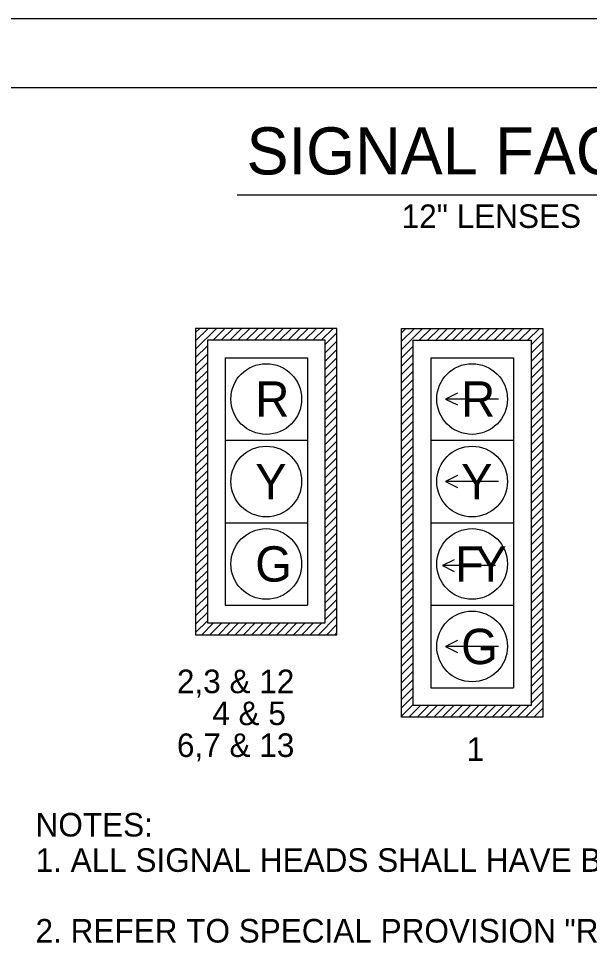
# Model space of a CAD drawing. Extents: x 1709451 to 1710451, y 561684 to 562324.
# Drawn here: x 1709624 to 1709720.9, y 562166.2 to 562324 of the extents above; entities that cross this region are included whole.
import ezdxf

# ---------------------------------------------------------------- set-up
doc = ezdxf.new("R2010")
doc.units = 0
for name, color, linetype in [('E_Existing ROW', 7, 'Continuous'), ('R_Alt Surface', 7, 'Continuous'), ('R_Alt Surface Annot', 7, 'Continuous'), ('R_Detour', 7, 'Continuous')]:
    doc.layers.add(name, color=color, linetype=linetype)

msp = doc.modelspace()

# ---------------------------------------------------------------- linework, layer by layer
at = {"layer": 'E_Existing ROW'}
for p, q in [((1709678.03, 562271.42), (1709654.03, 562271.42)), ((1709654.03, 562271.42), (1709654.03, 562219.42)), ((1709654.03, 562267.88), (1709657.57, 562271.42)), ((1709654.03, 562269.29), (1709656.16, 562271.42)), ((1709654.03, 562270.71), (1709654.74, 562271.42)), ((1709656.99, 562269.42), (1709658.99, 562271.42)), ((1709658.4, 562269.42), (1709660.4, 562271.42)), ((1709659.82, 562269.42), (1709661.82, 562271.42)), ((1709661.23, 562269.42), (1709663.23, 562271.42)), ((1709662.64, 562269.42), (1709664.64, 562271.42)), ((1709664.06, 562269.42), (1709666.06, 562271.42)), ((1709665.47, 562269.42), (1709667.47, 562271.42)), ((1709666.89, 562269.42), (1709668.89, 562271.42)), ((1709668.3, 562269.42), (1709670.3, 562271.42)), ((1709669.72, 562269.42), (1709671.72, 562271.42)), ((1709671.13, 562269.42), (1709673.13, 562271.42)), ((1709672.54, 562269.42), (1709674.54, 562271.42)), ((1709673.96, 562269.42), (1709675.96, 562271.42)), ((1709675.37, 562269.42), (1709677.37, 562271.42)), ((1709676.03, 562268.66), (1709678.03, 562270.66)), ((1709678.03, 562219.42), (1709678.03, 562271.42)), ((1709688.96, 562205.42), (1709688.96, 562271.42)), ((1709688.96, 562271.42), (1709712.96, 562271.42)), ((1709688.96, 562267.82), (1709692.57, 562271.42)), ((1709688.96, 562269.23), (1709691.16, 562271.42)), ((1709688.96, 562270.64), (1709689.74, 562271.42)), ((1709691.99, 562269.42), (1709693.99, 562271.42)), ((1709693.4, 562269.42), (1709695.4, 562271.42)), ((1709694.81, 562269.42), (1709696.81, 562271.42)), ((1709696.23, 562269.42), (1709698.23, 562271.42)), ((1709697.64, 562269.42), (1709699.64, 562271.42)), ((1709699.06, 562269.42), (1709701.06, 562271.42)), ((1709700.47, 562269.42), (1709702.47, 562271.42)), ((1709701.89, 562269.42), (1709703.89, 562271.42)), ((1709703.3, 562269.42), (1709705.3, 562271.42)), ((1709704.71, 562269.42), (1709706.71, 562271.42)), ((1709706.13, 562269.42), (1709708.13, 562271.42)), ((1709707.54, 562269.42), (1709709.54, 562271.42)), ((1709708.96, 562269.42), (1709710.96, 562271.42)), ((1709710.37, 562269.42), (1709712.37, 562271.42)), ((1709712.96, 562271.42), (1709712.96, 562205.42)), ((1709676.03, 562267.25), (1709678.03, 562269.25)), ((1709710.96, 562268.6), (1709712.96, 562270.6)), ((1709710.96, 562267.19), (1709712.96, 562269.19)), ((1709654.03, 562266.46), (1709656.03, 562268.46)), ((1709676.03, 562265.84), (1709678.03, 562267.84)), ((1709688.96, 562266.4), (1709690.96, 562268.4)), ((1709710.96, 562265.77), (1709712.96, 562267.77)), ((1709654.03, 562265.05), (1709656.03, 562267.05)), ((1709659.03, 562266.42), (1709673.03, 562266.42)), ((1709659.03, 562266.42), (1709659.03, 562252.42)), ((1709673.03, 562266.42), (1709673.03, 562252.42)), ((1709676.03, 562264.42), (1709678.03, 562266.42)), ((1709688.96, 562264.99), (1709690.96, 562266.99)), ((1709693.96, 562266.42), (1709707.96, 562266.42)), ((1709693.96, 562266.42), (1709693.96, 562252.42)), ((1709707.96, 562266.42), (1709707.96, 562252.42)), ((1709710.96, 562264.36), (1709712.96, 562266.36)), ((1709654.03, 562263.63), (1709656.03, 562265.63)), ((1709676.03, 562263.01), (1709678.03, 562265.01)), ((1709688.96, 562263.57), (1709690.96, 562265.57)), ((1709710.96, 562262.95), (1709712.96, 562264.95)), ((1709654.03, 562262.22), (1709656.03, 562264.22)), ((1709654.03, 562260.81), (1709656.03, 562262.81)), ((1709676.03, 562261.59), (1709678.03, 562263.59)), ((1709688.96, 562262.16), (1709690.96, 562264.16)), ((1709688.96, 562260.75), (1709690.96, 562262.75)), ((1709710.96, 562261.53), (1709712.96, 562263.53)), ((1709654.03, 562259.39), (1709656.03, 562261.39)), ((1709676.03, 562260.18), (1709678.03, 562262.18)), ((1709688.96, 562259.33), (1709690.96, 562261.33)), ((1709710.96, 562260.12), (1709712.96, 562262.12)), ((1709654.03, 562257.98), (1709656.03, 562259.98)), ((1709676.03, 562258.76), (1709678.03, 562260.76)), ((1709688.96, 562257.92), (1709690.96, 562259.92)), ((1709710.96, 562258.7), (1709712.96, 562260.7)), ((1709654.03, 562256.56), (1709656.03, 562258.56)), ((1709676.03, 562257.35), (1709678.03, 562259.35)), ((1709688.96, 562256.5), (1709690.96, 562258.5)), ((1709705.46, 562259.42), (1709696.46, 562259.42)), ((1709710.96, 562257.29), (1709712.96, 562259.29)), ((1709654.03, 562255.15), (1709656.03, 562257.15)), ((1709676.03, 562255.94), (1709678.03, 562257.94)), ((1709676.03, 562254.52), (1709678.03, 562256.52)), ((1709688.96, 562255.09), (1709690.96, 562257.09)), ((1709710.96, 562255.88), (1709712.96, 562257.88)), ((1709710.96, 562254.46), (1709712.96, 562256.46)), ((1709654.03, 562253.73), (1709656.03, 562255.73)), ((1709676.03, 562253.11), (1709678.03, 562255.11)), ((1709688.96, 562253.67), (1709690.96, 562255.67)), ((1709710.96, 562253.05), (1709712.96, 562255.05)), ((1709654.03, 562252.32), (1709656.03, 562254.32)), ((1709676.03, 562251.69), (1709678.03, 562253.69)), ((1709688.96, 562252.26), (1709690.96, 562254.26)), ((1709710.96, 562251.63), (1709712.96, 562253.63)), ((1709654.03, 562250.91), (1709656.03, 562252.91)), ((1709659.03, 562252.42), (1709673.03, 562252.42)), ((1709659.03, 562252.42), (1709659.03, 562238.42)), ((1709673.03, 562252.42), (1709673.03, 562238.42)), ((1709676.03, 562250.28), (1709678.03, 562252.28)), ((1709688.96, 562250.85), (1709690.96, 562252.85)), ((1709693.96, 562252.42), (1709707.96, 562252.42)), ((1709693.96, 562252.42), (1709693.96, 562238.42)), ((1709707.96, 562252.42), (1709707.96, 562238.42)), ((1709710.96, 562250.22), (1709712.96, 562252.22)), ((1709654.03, 562249.49), (1709656.03, 562251.49)), ((1709676.03, 562248.86), (1709678.03, 562250.86)), ((1709688.96, 562249.43), (1709690.96, 562251.43)), ((1709710.96, 562248.8), (1709712.96, 562250.8)), ((1709654.03, 562248.08), (1709656.03, 562250.08)), ((1709654.03, 562246.66), (1709656.03, 562248.66)), ((1709676.03, 562247.45), (1709678.03, 562249.45)), ((1709688.96, 562248.02), (1709690.96, 562250.02)), ((1709688.96, 562246.6), (1709690.96, 562248.6)), ((1709710.96, 562247.39), (1709712.96, 562249.39)), ((1709654.03, 562245.25), (1709656.03, 562247.25)), ((1709676.03, 562246.04), (1709678.03, 562248.04)), ((1709688.96, 562245.19), (1709690.96, 562247.19)), ((1709710.96, 562245.98), (1709712.96, 562247.98)), ((1709654.03, 562243.84), (1709656.03, 562245.84)), ((1709676.03, 562244.62), (1709678.03, 562246.62)), ((1709688.96, 562243.77), (1709690.96, 562245.77)), ((1709705.46, 562245.42), (1709696.46, 562245.42)), ((1709710.96, 562244.56), (1709712.96, 562246.56)), ((1709654.03, 562242.42), (1709656.03, 562244.42)), ((1709676.03, 562243.21), (1709678.03, 562245.21)), ((1709676.03, 562241.79), (1709678.03, 562243.79)), ((1709688.96, 562242.36), (1709690.96, 562244.36)), ((1709710.96, 562243.15), (1709712.96, 562245.15)), ((1709654.03, 562241.01), (1709656.03, 562243.01)), ((1709676.03, 562240.38), (1709678.03, 562242.38)), ((1709688.96, 562240.95), (1709690.96, 562242.95)), ((1709710.96, 562241.73), (1709712.96, 562243.73)), ((1709710.96, 562240.32), (1709712.96, 562242.32)), ((1709654.03, 562239.59), (1709656.03, 562241.59)), ((1709676.03, 562238.97), (1709678.03, 562240.97)), ((1709688.96, 562239.53), (1709690.96, 562241.53)), ((1709710.96, 562238.9), (1709712.96, 562240.9)), ((1709654.03, 562238.18), (1709656.03, 562240.18)), ((1709676.03, 562237.55), (1709678.03, 562239.55)), ((1709688.96, 562238.12), (1709690.96, 562240.12)), ((1709710.96, 562237.49), (1709712.96, 562239.49)), ((1709654.03, 562236.76), (1709656.03, 562238.76)), ((1709659.03, 562238.42), (1709673.03, 562238.42)), ((1709659.03, 562238.42), (1709659.03, 562224.42)), ((1709673.03, 562238.42), (1709673.03, 562224.42)), ((1709676.03, 562236.14), (1709678.03, 562238.14)), ((1709688.96, 562236.7), (1709690.96, 562238.7)), ((1709693.96, 562238.42), (1709707.96, 562238.42)), ((1709693.96, 562238.42), (1709693.96, 562224.42)), ((1709707.96, 562238.42), (1709707.96, 562224.42)), ((1709710.96, 562236.08), (1709712.96, 562238.08)), ((1709654.03, 562235.35), (1709656.03, 562237.35)), ((1709654.03, 562233.94), (1709656.03, 562235.94)), ((1709676.03, 562234.72), (1709678.03, 562236.72)), ((1709688.96, 562235.29), (1709690.96, 562237.29)), ((1709710.96, 562234.66), (1709712.96, 562236.66)), ((1709654.03, 562232.52), (1709656.03, 562234.52)), ((1709676.03, 562233.31), (1709678.03, 562235.31)), ((1709688.96, 562233.88), (1709690.96, 562235.88)), ((1709688.96, 562232.46), (1709690.96, 562234.46)), ((1709710.96, 562233.25), (1709712.96, 562235.25)), ((1709654.03, 562231.11), (1709656.03, 562233.11)), ((1709676.03, 562231.89), (1709678.03, 562233.89)), ((1709688.96, 562231.05), (1709690.96, 562233.05)), ((1709710.96, 562231.83), (1709712.96, 562233.83)), ((1709654.03, 562229.69), (1709656.03, 562231.69)), ((1709676.03, 562230.48), (1709678.03, 562232.48)), ((1709688.96, 562229.63), (1709690.96, 562231.63)), ((1709710.96, 562230.42), (1709712.96, 562232.42)), ((1709654.03, 562228.28), (1709656.03, 562230.28)), ((1709676.03, 562229.07), (1709678.03, 562231.07)), ((1709676.03, 562227.65), (1709678.03, 562229.65)), ((1709688.96, 562228.22), (1709690.96, 562230.22)), ((1709704.94, 562231.15), (1709695.94, 562231.15)), ((1709710.96, 562229.01), (1709712.96, 562231.01)), ((1709710.96, 562227.59), (1709712.96, 562229.59)), ((1709654.03, 562226.86), (1709656.03, 562228.86)), ((1709676.03, 562226.24), (1709678.03, 562228.24)), ((1709688.96, 562226.8), (1709690.96, 562228.8)), ((1709710.96, 562226.18), (1709712.96, 562228.18)), ((1709654.03, 562225.45), (1709656.03, 562227.45)), ((1709676.03, 562224.82), (1709678.03, 562226.82)), ((1709688.96, 562225.39), (1709690.96, 562227.39)), ((1709710.96, 562224.76), (1709712.96, 562226.76)), ((1709654.03, 562224.04), (1709656.03, 562226.04)), ((1709676.03, 562223.41), (1709678.03, 562225.41)), ((1709688.96, 562223.98), (1709690.96, 562225.98)), ((1709710.96, 562223.35), (1709712.96, 562225.35)), ((1709654.03, 562222.62), (1709656.03, 562224.62)), ((1709659.03, 562224.42), (1709673.03, 562224.42)), ((1709676.03, 562221.99), (1709678.03, 562223.99)), ((1709688.96, 562222.56), (1709690.96, 562224.56)), ((1709693.96, 562224.42), (1709707.96, 562224.42)), ((1709693.96, 562224.42), (1709693.96, 562210.42)), ((1709707.96, 562224.42), (1709707.96, 562210.42)), ((1709710.96, 562221.93), (1709712.96, 562223.93)), ((1709654.03, 562221.21), (1709656.03, 562223.21)), ((1709654.03, 562219.79), (1709656.03, 562221.79)), ((1709674.87, 562219.42), (1709678.03, 562222.58)), ((1709688.96, 562221.15), (1709690.96, 562223.15)), ((1709688.96, 562219.73), (1709690.96, 562221.73)), ((1709710.96, 562220.52), (1709712.96, 562222.52)), ((1709655.07, 562219.42), (1709657.07, 562221.42)), ((1709656.48, 562219.42), (1709658.48, 562221.42)), ((1709657.9, 562219.42), (1709659.9, 562221.42)), ((1709659.31, 562219.42), (1709661.31, 562221.42)), ((1709660.73, 562219.42), (1709662.73, 562221.42)), ((1709662.14, 562219.42), (1709664.14, 562221.42)), ((1709663.56, 562219.42), (1709665.56, 562221.42)), ((1709664.97, 562219.42), (1709666.97, 562221.42)), ((1709666.38, 562219.42), (1709668.38, 562221.42)), ((1709667.8, 562219.42), (1709669.8, 562221.42)), ((1709669.21, 562219.42), (1709671.21, 562221.42)), ((1709670.63, 562219.42), (1709672.63, 562221.42)), ((1709672.04, 562219.42), (1709674.04, 562221.42)), ((1709673.46, 562219.42), (1709675.46, 562221.42)), ((1709676.28, 562219.42), (1709678.03, 562221.17)), ((1709688.96, 562218.32), (1709690.96, 562220.32)), ((1709710.96, 562219.11), (1709712.96, 562221.11)), ((1709654.03, 562219.42), (1709678.03, 562219.42)), ((1709677.7, 562219.42), (1709678.03, 562219.75)), ((1709688.96, 562216.9), (1709690.96, 562218.9)), ((1709710.96, 562217.69), (1709712.96, 562219.69)), ((1709688.96, 562215.49), (1709690.96, 562217.49)), ((1709705.46, 562217.42), (1709696.46, 562217.42)), ((1709710.96, 562216.28), (1709712.96, 562218.28)), ((1709688.96, 562214.08), (1709690.96, 562216.08)), ((1709710.96, 562214.86), (1709712.96, 562216.86)), ((1709710.96, 562213.45), (1709712.96, 562215.45)), ((1709688.96, 562212.66), (1709690.96, 562214.66)), ((1709710.96, 562212.03), (1709712.96, 562214.03)), ((1709688.96, 562211.25), (1709690.96, 562213.25)), ((1709710.96, 562210.62), (1709712.96, 562212.62)), ((1709688.96, 562209.83), (1709690.96, 562211.83)), ((1709710.96, 562209.21), (1709712.96, 562211.21)), ((1709688.96, 562208.42), (1709690.96, 562210.42)), ((1709693.96, 562210.42), (1709707.96, 562210.42)), ((1709710.96, 562207.79), (1709712.96, 562209.79)), ((1709688.96, 562207.01), (1709690.96, 562209.01)), ((1709688.96, 562205.59), (1709690.96, 562207.59)), ((1709710.01, 562205.42), (1709712.96, 562208.38)), ((1709690.21, 562205.42), (1709692.21, 562207.42)), ((1709691.63, 562205.42), (1709693.63, 562207.42)), ((1709693.04, 562205.42), (1709695.04, 562207.42)), ((1709694.45, 562205.42), (1709696.45, 562207.42)), ((1709695.87, 562205.42), (1709697.87, 562207.42)), ((1709697.28, 562205.42), (1709699.28, 562207.42)), ((1709698.7, 562205.42), (1709700.7, 562207.42)), ((1709700.11, 562205.42), (1709702.11, 562207.42)), ((1709701.52, 562205.42), (1709703.52, 562207.42)), ((1709702.94, 562205.42), (1709704.94, 562207.42)), ((1709704.35, 562205.42), (1709706.35, 562207.42)), ((1709705.77, 562205.42), (1709707.77, 562207.42)), ((1709707.18, 562205.42), (1709709.18, 562207.42)), ((1709708.6, 562205.42), (1709710.6, 562207.42)), ((1709711.42, 562205.42), (1709712.96, 562206.96)), ((1709712.96, 562205.42), (1709688.96, 562205.42)), ((1709712.84, 562205.42), (1709712.96, 562205.55))]:
    msp.add_line(p, q, dxfattribs=at)
for points in [[(1709676.03, 562221.42), (1709676.03, 562269.42), (1709656.03, 562269.42), (1709656.03, 562221.42)], [(1709690.96, 562207.42), (1709690.96, 562269.42), (1709710.96, 562269.42), (1709710.96, 562207.42)]]:
    msp.add_lwpolyline(points, close=True, dxfattribs=at)
for points in [[(1709698.46, 562260.42), (1709696.46, 562259.42), (1709698.46, 562258.42)], [(1709698.46, 562246.42), (1709696.46, 562245.42), (1709698.46, 562244.42)], [(1709697.94, 562232.15), (1709695.94, 562231.15), (1709697.94, 562230.15)], [(1709698.46, 562218.42), (1709696.46, 562217.42), (1709698.46, 562216.42)]]:
    msp.add_lwpolyline(points, dxfattribs=at)
for centre in [(1709666.03, 562259.42), (1709700.96, 562259.42), (1709666.03, 562245.42), (1709700.96, 562245.42), (1709666.03, 562231.42), (1709700.96, 562231.42), (1709700.96, 562217.42)]:
    msp.add_circle(centre, 6, dxfattribs=at)
at = {"layer": 'R_Alt Surface'}
msp.add_line((1709488.22, 562312.31), (1710436.76, 562312.31), dxfattribs=at)
at = {"layer": 'R_Alt Surface Annot'}
msp.add_line((1709451.02, 562324), (1710451.02, 562324), dxfattribs=at)
msp.add_lwpolyline([(1709451, 562324), (1710451.02, 562324), (1710451.02, 561683.98), (1709451, 561683.98)], close=True, dxfattribs=at)
at = {"layer": 'R_Detour'}
msp.add_line((1709661.08, 562294.07), (1709759.27, 562294.07), dxfattribs=at)

# ---------------------------------------------------------------- texts
at = {"layer": 'E_Existing ROW'}
msp.add_text('12" LENSES', height=4, rotation=0.072, dxfattribs=at).set_placement((1709689.01, 562288.44))
for s, p in [('R', (1709664.16, 562256.42)), ('R', (1709699.1, 562256.42)), ('Y', (1709664.14, 562242.42)), ('Y', (1709699.08, 562242.42)), ('G', (1709664.16, 562228.42)), ('F', (1709698.06, 562228.42)), ('Y', (1709701.48, 562228.42)), ('G', (1709699.1, 562214.42))]:
    msp.add_text(s, height=6, dxfattribs=at).set_placement(p)
at = {"layer": 'R_Detour'}
for s, height, p in [('SIGNAL FACES', 8, (1709662.68, 562297.54)), ('2,3 & 12', 4, (1709650.87, 562209.49)), ('4 & 5', 4, (1709656.87, 562204.07)), ('6,7 & 13', 4, (1709650.87, 562198.66)), ('1', 4, (1709700.04, 562197.99)), ('NOTES:', 4, (1709626.88, 562185.16)), ('1. ALL SIGNAL HEADS SHALL HAVE BACKPLATES.', 4, (1709626.88, 562179.16)), ('2. REFER TO SPECIAL PROVISION "RETROREFLECTIVE', 4, (1709626.88, 562167.16))]:
    msp.add_text(s, height=height, dxfattribs=at).set_placement(p)

doc.saveas('drawing.dxf')
